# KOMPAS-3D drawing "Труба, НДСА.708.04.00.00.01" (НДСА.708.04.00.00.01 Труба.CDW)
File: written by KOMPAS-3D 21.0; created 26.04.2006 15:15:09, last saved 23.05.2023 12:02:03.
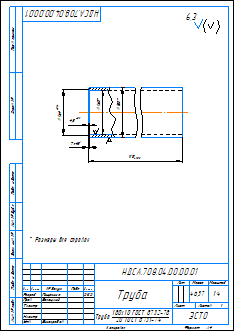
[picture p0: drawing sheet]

Sheet 1: A4, portrait

Document properties: Полное имя файла: НДСА.708.04.00.00.01 Труба.m3d; Автор: Устинов А.В.; Организация: Эсто-вакуум; 247609406538: <item xmlns="http://appius.ru/pdm" xmlns:xs="http://www.w3.org/2001/XMLSchema" xmlns:xsi="http://www.w3.org/2001/XMLSchema-instance" xsi:type="item">  <element xmlns:d2p1="http://v8.1c.ru/8.1/data/enterprise/current-config" xsi:type="d2p1:CatalogRef.aps_Элемен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; PLM_CDWXDTO: <item xmlns="http://appius.ru/pdm" xmlns:xs="http://www.w3.org/2001/XMLSchema" xmlns:xsi="http://www.w3.org/2001/XMLSchema-instance" xsi:type="item">  <element xmlns:d2p1="http://v8.1c.ru/8.1/data/enterprise/current-config" xsi:type="d2p1:CatalogRef.aps_Элемен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; Масса: 46.57347; Знак неуказанной шероховатости: 4; Параметр неуказанной шероховатости: 6,3; 247609406838: <item xmlns="http://appius.ru/pdm" xmlns:xs="http://www.w3.org/2001/XMLSchema" xmlns:xsi="http://www.w3.org/2001/XMLSchema-instance" xsi:type="item">  <element xmlns:d2p1="http://v8.1c.ru/8.1/data/enterprise/current-config" xsi:type="d2p1:CatalogRef.aps_Элемен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; 247609406938: <item xmlns="http://appius.ru/pdm" xmlns:xs="http://www.w3.org/2001/XMLSchema" xmlns:xsi="http://www.w3.org/2001/XMLSchema-instance" xsi:type="item">  <element xmlns:d2p1="http://v8.1c.ru/8.1/data/enterprise/current-config" xsi:type="d2p1:CatalogRef.aps_Элемен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; 247609407038: <item xmlns="http://appius.ru/pdm" xmlns:xs="http://www.w3.org/2001/XMLSchema" xmlns:xsi="http://www.w3.org/2001/XMLSchema-instance" xsi:type="item">  <element xmlns:d2p1="http://v8.1c.ru/8.1/data/enterprise/current-config" xsi:type="d2p1:CatalogRef.aps_Элемен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; PDM_DOCXDTO: <item xmlns="http://appius.ru/pdm" xmlns:xs="http://www.w3.org/2001/XMLSchema" xmlns:xsi="http://www.w3.org/2001/XMLSchema-instance" xsi:type="item">  <element xmlns:d2p1="http://v8.1c.ru/8.1/data/enterprise/current-config" xsi:type="d2p1:CatalogRef.aps_Элемен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; PDM_ITEMXDTO: <item xmlns="http://appius.ru/pdm" xmlns:xs="http://www.w3.org/2001/XMLSchema" xmlns:xsi="http://www.w3.org/2001/XMLSchema-instance" xsi:type="item">  <element xmlns:d2p1="http://v8.1c.ru/8.1/data/enterprise/current-config" xsi:type="d2p1:CatalogRef.aps_Элемен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; PDM_DRAWINGXDTO: <item xmlns="http://appius.ru/pdm" xmlns:xs="http://www.w3.org/2001/XMLSchema" xmlns:xsi="http://www.w3.org/2001/XMLSchema-instance" xsi:type="item">  <element xmlns:d2p1="http://v8.1c.ru/8.1/data/enterprise/current-config" xsi:type="d2p1:CatalogRef.aps_Элемен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

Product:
- Part/product: Труба  | designation НДСА.708.04.00.00.01
    Материал: Труба$d180х10 ГОСТ 8732-78;20 ГОСТ 8731-74$ (density 7859 kg/m3)
    Масса: 46.57347
    additional columns: <item xmlns="http://appius.ru/pdm" xmlns:xs="http://www.w3.org/2001/XMLSchema" x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; <item xmlns="http://appius.ru/pdm" xmlns:xs="http://www.w3.org/2001/XMLSchema" x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; <item xmlns="http://appius.ru/pdm" xmlns:xs="http://www.w3.org/2001/XMLSchema" x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

Title block, sheet 1: Наименование: Труба; designation: НДСА.708.04.00.00.01; Материал: Труба 180х10 ГОСТ 8732-78 20 ГОСТ 8731-74; Масса: 46,57; scale: 1:4; Количество листов документа: 1; organisation: ЭСТО; Форматы листов документа: A4; stored path: D:\WorkPDM\Устинов А.В\adef4302-e6d0-4e78-a7d0-57c469fcab05\УКРД.789.01.05.00.01 Труба.cdw; Разработал: Пищагина; Проверил: Белецкий; Утвердил: Виноградов; Разработал, date: 23.05.23
Table, sheet 1:
  0;Material:V399CD8922A934364BF9D3DB1A16B3F75;Sortament:VACA86AD6B524487FA06521D22EE88F1C^SortamentEx:VA444AFA89AC74945B3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

Views: Вид 1, Спереди, Проекционный вид 3, Местный разрез 1
Referenced files in C:\Users\s.pischagina\Desktop\PLM\: НДСА.708.04.00.00.01 Труба.m3d
Referenced files in E:\НДСА.014.01.08.00.00 Гидроподъемник\: НДСА.014.01.08.05.02 Труба.m3d
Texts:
  НДСА.708.04.00.00.01 Труба
Dimensions and other numbers on the sheet: 1113; 180; 160; 164; 4,5; 7; 6,3; 1:4; 46,57; 23.05.23; 1

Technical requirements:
  * Размеры для справок.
